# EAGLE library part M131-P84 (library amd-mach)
AMD MACH SERIES
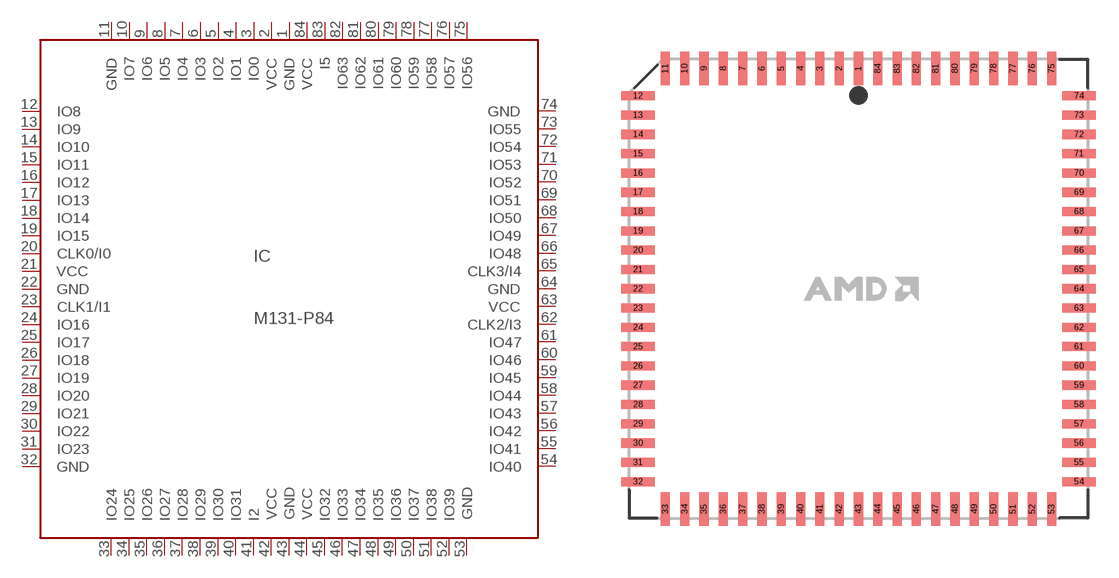
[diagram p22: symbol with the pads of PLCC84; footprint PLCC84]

Designator prefix IC

## M131-P84 (OC_FARNELL: unknown; OC_NEWARK: unknown)  [PLCC84]
1  GND  pwr
2  VCC  pwr
3  IO0
4  IO1
5  IO2
6  IO3
7  IO4
8  IO5
9  IO6
10  IO7
11  GND  pwr
12  IO8
13  IO9
14  IO10
15  IO11
16  IO12
17  IO13
18  IO14
19  IO15
20  CLK0/I0  in
21  VCC  pwr
22  GND  pwr
23  CLK1/I1  in
24  IO16
25  IO17
26  IO18
27  IO19
28  IO20
29  IO21
30  IO22
31  IO23
32  GND  pwr
33  IO24
34  IO25
35  IO26
36  IO27
37  IO28
38  IO29
39  IO30
40  IO31
41  I2  in
42  VCC  pwr
43  GND  pwr
44  VCC  pwr
45  IO32
46  IO33
47  IO34
48  IO35
49  IO36
50  IO37
51  IO38
52  IO39
53  GND  pwr
54  IO40
55  IO41
56  IO42
57  IO43
58  IO44
59  IO45
60  IO46
61  IO47
62  CLK2/I3  in
63  VCC  pwr
64  GND  pwr
65  CLK3/I4  in
66  IO48
67  IO49
68  IO50
69  IO51
70  IO52
71  IO53
72  IO54
73  IO55
74  GND  pwr
75  IO56
76  IO57
77  IO58
78  IO59
79  IO60
80  IO61
81  IO62
82  IO63
83  I5  in
84  VCC  pwr

## Footprint PLCC84 (pad centres in mm)
PLASTIC LEADED CHIP CARRIER
smd 0.6 x 2.2: 1 0,14.5; 2 -1.27,14.5; 3 -2.54,14.5; 4 -3.81,14.5; 5 -5.08,14.5; 6 -6.35,14.5; 7 -7.62,14.5; 8 -8.89,14.5; 9 -10.16,14.5; 10 -11.43,14.5; 11 -12.7,14.5; 33 -12.7,-14.5; 34 -11.43,-14.5; 35 -10.16,-14.5; 36 -8.89,-14.5; 37 -7.62,-14.5; 38 -6.35,-14.5; 39 -5.08,-14.5; 40 -3.81,-14.5; 41 -2.54,-14.5; 42 -1.27,-14.5; 43 0,-14.5; 44 1.27,-14.5; 45 2.54,-14.5; 46 3.81,-14.5; 47 5.08,-14.5; 48 6.35,-14.5; 49 7.62,-14.5; 50 8.89,-14.5; 51 10.16,-14.5; 52 11.43,-14.5; 53 12.7,-14.5; 75 12.7,14.5; 76 11.43,14.5; 77 10.16,14.5; 78 8.89,14.5; 79 7.62,14.5; 80 6.35,14.5; 81 5.08,14.5; 82 3.81,14.5; 83 2.54,14.5; 84 1.27,14.5
smd 2.2 x 0.6: 12 -14.5,12.7; 13 -14.5,11.43; 14 -14.5,10.16; 15 -14.5,8.89; 16 -14.5,7.62; 17 -14.5,6.35; 18 -14.5,5.08; 19 -14.5,3.81; 20 -14.5,2.54; 21 -14.5,1.27; 22 -14.5,0; 23 -14.5,-1.27; 24 -14.5,-2.54; 25 -14.5,-3.81; 26 -14.5,-5.08; 27 -14.5,-6.35; 28 -14.5,-7.62; 29 -14.5,-8.89; 30 -14.5,-10.16; 31 -14.5,-11.43; 32 -14.5,-12.7; 54 14.5,-12.7; 55 14.5,-11.43; 56 14.5,-10.16; 57 14.5,-8.89; 58 14.5,-7.62; 59 14.5,-6.35; 60 14.5,-5.08; 61 14.5,-3.81; 62 14.5,-2.54; 63 14.5,-1.27; 64 14.5,0; 65 14.5,1.27; 66 14.5,2.54; 67 14.5,3.81; 68 14.5,5.08; 69 14.5,6.35; 70 14.5,7.62; 71 14.5,8.89; 72 14.5,10.16; 73 14.5,11.43; 74 14.5,12.7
